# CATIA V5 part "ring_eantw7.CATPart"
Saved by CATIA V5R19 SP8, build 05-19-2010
Part number: ring_eantw7
Nomenclature: 70_j
Source: Unknown
Description: PART-ring_eantw7-DESC
Bounding box of the stored display mesh (mm): x -7 to 7, y -4.971 to 7, z 0 to 0.8
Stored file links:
  C:\Users\rphgr\Desktop\0_Tapis_TC520B_vitesse\ring_eantw7.CATPart
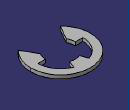
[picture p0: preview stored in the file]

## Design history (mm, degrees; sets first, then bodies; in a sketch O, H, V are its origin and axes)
Body1 "ring_eantw7" (main body)
  Solid1: solid without history
  AxisSystem1: origin (0, 0, 0), X (1, 0, 0), Y (0, 1, 0), Z (0, 0, 1)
